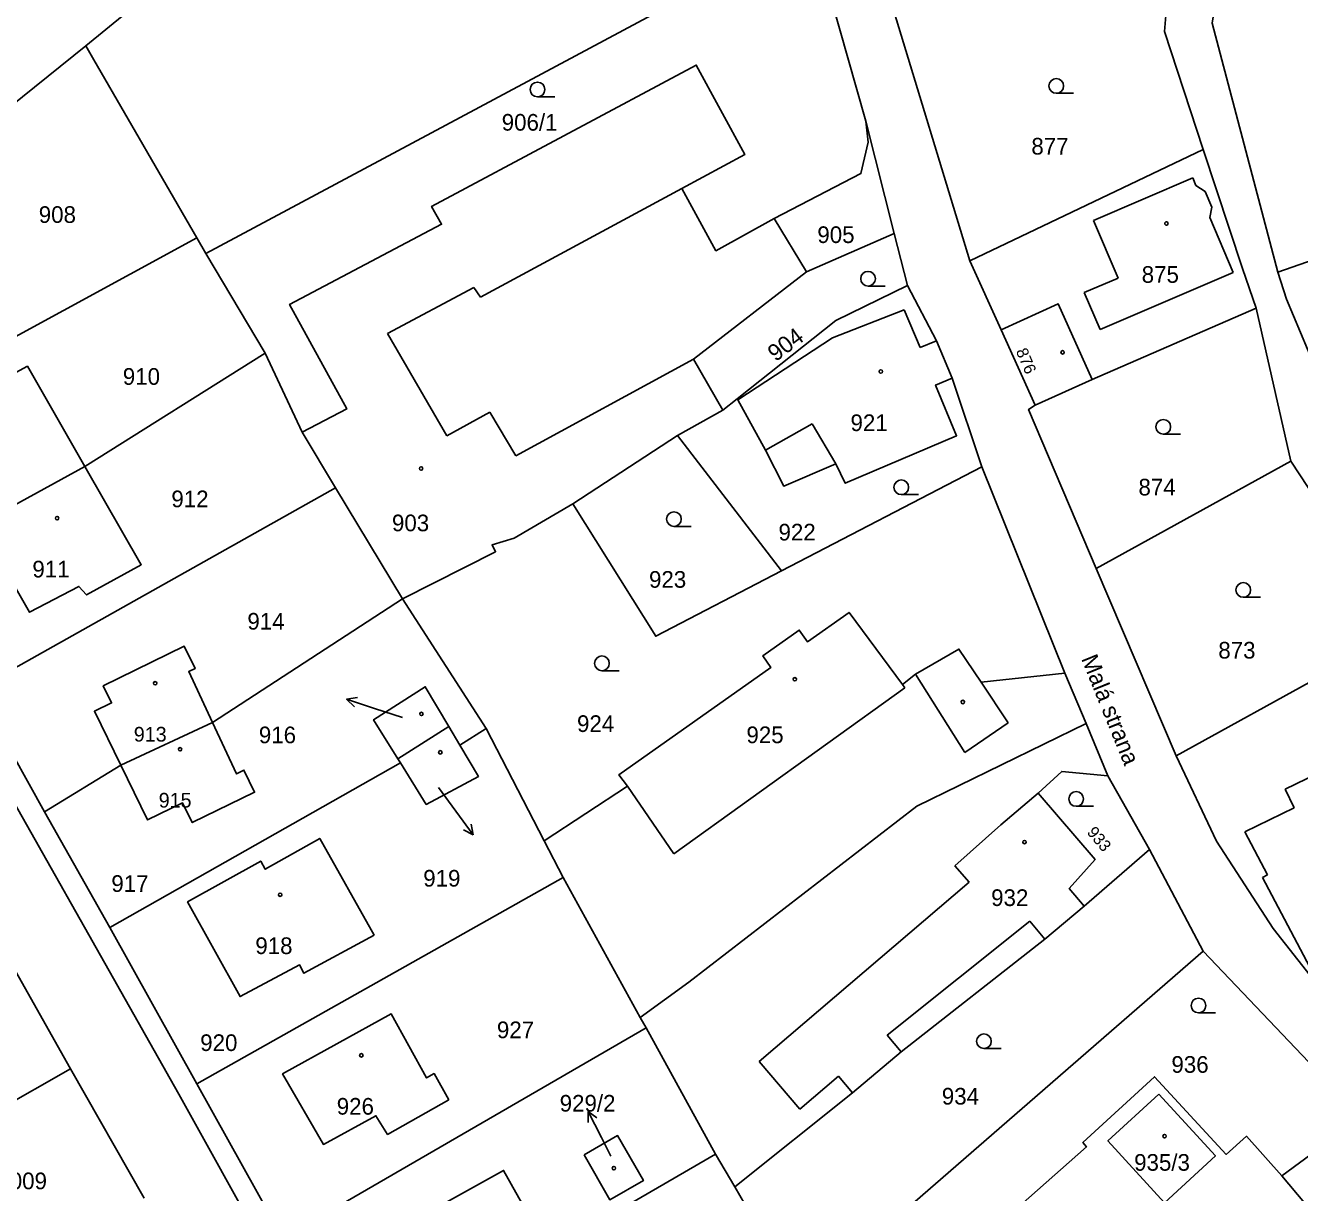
# Model space of a CAD drawing. Extents: x -504988 to -494607, y -1123820 to -1114018.
# Drawn here: x -497675.7 to -497545.8, y -1120128.9 to -1120009.8 of the extents above; entities that cross this region are included whole.
import ezdxf

# ---------------------------------------------------------------- set-up
doc = ezdxf.new("R2010")
doc.units = 0
for name, color, linetype in [('Hranice parcel', 7, 'Continuous'), ('Parcelní čísla', 7, 'Continuous'), ('Pop  PČ popisy', 7, 'Continuous'), ('Vnitřní kresba', 7, 'Continuous'), ('Značky budov', 7, 'Continuous'), ('Značky kultur', 7, 'Continuous')]:
    doc.layers.add(name, color=color, linetype=linetype)

msp = doc.modelspace()

# ---------------------------------------------------------------- linework, layer by layer
at = {"layer": 'Hranice parcel'}
for p, q in [((-497595.51, -1120000.03), (-497657.25, -1120033.08)), ((-497595.51, -1120000.03), (-497589.97, -1120019.6)), ((-497588.93, -1120002.38), (-497579.36, -1120033.84)), ((-497669.5, -1120011.91), (-497661.03, -1120004.98)), ((-497686.75, -1120025.78), (-497669.5, -1120011.91)), ((-497589.97, -1120019.6), (-497587.08, -1120031.04)), ((-497555.57, -1120022.47), (-497579.36, -1120033.84)), ((-497528.79, -1120028.34), (-497547.97, -1120034.99)), ((-497596.03, -1120034.95), (-497599.31, -1120029.53)), ((-497695.36, -1120051.78), (-497658.2, -1120031.49)), ((-497657.25, -1120033.08), (-497658.2, -1120031.49)), ((-497587.08, -1120031.04), (-497596.03, -1120034.95)), ((-497587.08, -1120031.04), (-497585.74, -1120036.35)), ((-497651.22, -1120043.25), (-497657.25, -1120033.08)), ((-497579.36, -1120033.84), (-497576.19, -1120040.86)), ((-497550.18, -1120038.67), (-497566.89, -1120045.94)), ((-497550.18, -1120038.67), (-497546.66, -1120054.28)), ((-497576.19, -1120040.86), (-497572.72, -1120048.57)), ((-497669.6, -1120054.8), (-497651.22, -1120043.25)), ((-497647.44, -1120051.31), (-497651.22, -1120043.25)), ((-497581.17, -1120045.81), (-497578.15, -1120054.86)), ((-497566.89, -1120045.94), (-497572.72, -1120048.57)), ((-497604.55, -1120049.07), (-497603.08, -1120047.91)), ((-497609.19, -1120051.65), (-497604.55, -1120049.07)), ((-497647.44, -1120051.31), (-497644.03, -1120056.98)), ((-497619.86, -1120058.62), (-497609.19, -1120051.65)), ((-497609.19, -1120051.65), (-497598.56, -1120065.46)), ((-497680.39, -1120060.73), (-497669.6, -1120054.8)), ((-497598.56, -1120065.46), (-497578.15, -1120054.86)), ((-497578.15, -1120054.86), (-497569.69, -1120075.9)), ((-497546.66, -1120054.28), (-497566.51, -1120065.23)), ((-497680.65, -1120077.57), (-497644.03, -1120056.98)), ((-497644.03, -1120056.98), (-497637.2, -1120068.32)), ((-497566.51, -1120065.23), (-497558.33, -1120084.33)), ((-497656.59, -1120080.92), (-497637.2, -1120068.32)), ((-497628.7, -1120081.55), (-497637.2, -1120068.32)), ((-497537.01, -1120072.53), (-497558.33, -1120084.33)), ((-497569.69, -1120075.9), (-497567.53, -1120081.03)), ((-497680.65, -1120077.57), (-497673.72, -1120090.03)), ((-497665.93, -1120085.28), (-497656.59, -1120080.92)), ((-497567.53, -1120081.03), (-497565.3, -1120086.35)), ((-497637.69, -1120084.62), (-497632.49, -1120081.33)), ((-497632.49, -1120081.33), (-497631.36, -1120083.23)), ((-497631.36, -1120083.23), (-497628.7, -1120081.55)), ((-497622.76, -1120093), (-497628.7, -1120081.55)), ((-497637.43, -1120085.04), (-497637.69, -1120084.62)), ((-497673.72, -1120090.03), (-497665.93, -1120085.28)), ((-497667.07, -1120101.84), (-497637.43, -1120085.04)), ((-497565.3, -1120086.35), (-497561.06, -1120093.89)), ((-497673.72, -1120090.03), (-497667.07, -1120101.84)), ((-497620.83, -1120096.73), (-497622.76, -1120093)), ((-497567.71, -1120099.67), (-497561.06, -1120093.89)), ((-497561.06, -1120093.89), (-497555.6, -1120104.26)), ((-497658.18, -1120117.79), (-497620.83, -1120096.73)), ((-497620.83, -1120096.73), (-497612.97, -1120111.02)), ((-497667.07, -1120101.84), (-497658.18, -1120117.79)), ((-497596.6, -1120139.88), (-497555.6, -1120104.26)), ((-497555.6, -1120104.26), (-497539.48, -1120121.18)), ((-497677.63, -1120104.59), (-497671.08, -1120116.23)), ((-497649.42, -1120133.52), (-497612.36, -1120112.05)), ((-497612.36, -1120112.05), (-497612.97, -1120111.02)), ((-497612.36, -1120112.05), (-497605.3, -1120124.94)), ((-497671.08, -1120116.23), (-497708.88, -1120137.79)), ((-497671.08, -1120116.23), (-497663.57, -1120129.44)), ((-497658.18, -1120117.79), (-497649.42, -1120133.52)), ((-497547.56, -1120127.17), (-497539.48, -1120121.18)), ((-497605.3, -1120124.94), (-497622.27, -1120134.79)), ((-497603.34, -1120128.29), (-497605.3, -1120124.94)), ((-497543.02, -1120132.55), (-497547.56, -1120127.17)), ((-497598.04, -1120137.4), (-497603.34, -1120128.29))]:
    msp.add_line(p, q, dxfattribs=at)
for points in [[(-497547.97, -1120034.99), (-497554.66, -1120009.59), (-497552.95, -1119999.09)], [(-497559.23, -1120006.74), (-497559.51, -1120010.45), (-497555.57, -1120022.47)], [(-497658.2, -1120031.49), (-497668.68, -1120013.34), (-497669.5, -1120011.91)], [(-497599.31, -1120029.53), (-497605.26, -1120032.81), (-497608.75, -1120026.47), (-497602.33, -1120023), (-497607.26, -1120013.88), (-497634.25, -1120028.28), (-497633.23, -1120030.1), (-497648.72, -1120038.29), (-497642.9, -1120048.94), (-497647.44, -1120051.31)], [(-497589.97, -1120019.6), (-497589.74, -1120021.75), (-497590.48, -1120024.94), (-497599.31, -1120029.53)], [(-497555.57, -1120022.47), (-497551.59, -1120034.63), (-497550.18, -1120038.67)], [(-497604.55, -1120049.07), (-497607.55, -1120043.87), (-497596.03, -1120034.95)], [(-497547.97, -1120034.99), (-497547.09, -1120037.76), (-497541.37, -1120051.36)], [(-497603.08, -1120047.91), (-497593.03, -1120039.92), (-497585.74, -1120036.35)], [(-497585.74, -1120036.35), (-497582.76, -1120041.98), (-497581.17, -1120045.81)], [(-497565.3, -1120246.14), (-497589.23, -1120223.42), (-497599.85, -1120212.32), (-497616.68, -1120192.01), (-497627.04, -1120177.2), (-497636.91, -1120159.82), (-497651.33, -1120134.51), (-497660.03, -1120118.82), (-497706.21, -1120037.1)], [(-497576.19, -1120040.86), (-497570.36, -1120038.23), (-497566.89, -1120045.94)], [(-497669.6, -1120054.8), (-497675.46, -1120044.59), (-497680.85, -1120047.49), (-497680.18, -1120048.78), (-497685.55, -1120051.79), (-497680.39, -1120060.73)], [(-497603.08, -1120047.91), (-497603.02, -1120048.02), (-497600.22, -1120053.16), (-497598.35, -1120056.81), (-497593.05, -1120054.54), (-497592.07, -1120056.53), (-497580.72, -1120051.68), (-497582.87, -1120046.51), (-497581.17, -1120045.81)], [(-497572.72, -1120048.57), (-497573.39, -1120048.99), (-497566.51, -1120065.23)], [(-497680.39, -1120060.73), (-497675.23, -1120069.68), (-497670.2, -1120067.05), (-497669.42, -1120067.91), (-497663.85, -1120064.83), (-497669.6, -1120054.8)], [(-497546.66, -1120054.28), (-497540.5, -1120063.61), (-497537.01, -1120072.53)], [(-497637.2, -1120068.32), (-497627.72, -1120063.5), (-497628.09, -1120062.79), (-497625.84, -1120062.11), (-497619.86, -1120058.62)], [(-497619.86, -1120058.62), (-497611.39, -1120072.13), (-497598.56, -1120065.46)], [(-497622.76, -1120093), (-497614.27, -1120087.42), (-497615.17, -1120086.27), (-497599.65, -1120075.31), (-497600.48, -1120074.13), (-497596.77, -1120071.5), (-497595.93, -1120072.69), (-497591.68, -1120069.69), (-497586.25, -1120077.06), (-497584.93, -1120075.98), (-497580.48, -1120073.43), (-497578.23, -1120076.8), (-497569.69, -1120075.9)], [(-497656.59, -1120080.92), (-497659, -1120075.73), (-497658.37, -1120075.42), (-497659.46, -1120073.15), (-497667.72, -1120077.19), (-497666.87, -1120078.92), (-497668.63, -1120079.78), (-497665.93, -1120085.28)], [(-497632.49, -1120081.33), (-497634.89, -1120077.28), (-497640.16, -1120080.64), (-497637.69, -1120084.62)], [(-497665.93, -1120085.28), (-497663.21, -1120090.86), (-497659.63, -1120089.12), (-497658.65, -1120091.13), (-497652.3, -1120088.03), (-497653.38, -1120085.78), (-497654.15, -1120086.16), (-497656.59, -1120080.92)], [(-497612.97, -1120111.02), (-497608.02, -1120107.42), (-497584.77, -1120089.47), (-497567.53, -1120081.03)], [(-497637.43, -1120085.04), (-497634.79, -1120089.28), (-497629.47, -1120086.42), (-497631.36, -1120083.23)], [(-497558.33, -1120084.33), (-497554.21, -1120093.02), (-497548.46, -1120101.92), (-497543.43, -1120108.32)], [(-497567.71, -1120099.67), (-497569.23, -1120097.85), (-497566.61, -1120094.9), (-497572.39, -1120088.12), (-497570, -1120085.92), (-497565.3, -1120086.35)], [(-497640.12, -1120102.62), (-497645.65, -1120092.74), (-497651.21, -1120095.89), (-497651.67, -1120095.06), (-497659.12, -1120099.23), (-497653.78, -1120108.88), (-497647.7, -1120105.65), (-497647.27, -1120106.5), (-497640.12, -1120102.62)], [(-497603.34, -1120128.29), (-497591.33, -1120118.68), (-497586.38, -1120114.5), (-497571.74, -1120103.01), (-497567.71, -1120099.67)], [(-497632.49, -1120119.42), (-497634, -1120116.73), (-497634.76, -1120117.17), (-497638.38, -1120110.63), (-497649.44, -1120116.77), (-497645.27, -1120123.96), (-497639.93, -1120121.03), (-497638.73, -1120122.93), (-497632.49, -1120119.42)], [(-497547.56, -1120127.17), (-497551.18, -1120123.12), (-497553.25, -1120124.98), (-497560.54, -1120117.05), (-497567.85, -1120123.76), (-497567.49, -1120124.21), (-497592.77, -1120146.58)], [(-497560.09, -1120118.82), (-497554.33, -1120125.13), (-497559.51, -1120129.92), (-497565.3, -1120123.6), (-497560.09, -1120118.82)], [(-497618.71, -1120125.01), (-497615.29, -1120123.05), (-497612.66, -1120127.65), (-497616.08, -1120129.6), (-497618.71, -1120125.01)], [(-497622.27, -1120134.79), (-497624.28, -1120131.33), (-497626.91, -1120126.6), (-497638.61, -1120133.1), (-497633.81, -1120141.47)]]:
    msp.add_lwpolyline(points, dxfattribs=at)
at = {"layer": 'Pop  PČ popisy'}
for p, q in [((-497642.91, -1120078.55), (-497641.81, -1120078.39)), ((-497640.06, -1120079.48), (-497642.91, -1120078.55)), ((-497642.91, -1120078.55), (-497642.12, -1120079.34)), ((-497637.21, -1120080.41), (-497640.06, -1120079.48)), ((-497633.55, -1120087.54), (-497631.78, -1120089.96)), ((-497631.78, -1120089.96), (-497630.02, -1120092.39)), ((-497630.02, -1120092.39), (-497630.2, -1120091.28)), ((-497630.02, -1120092.39), (-497631.01, -1120091.87)), ((-497616.93, -1120123.26), (-497618.29, -1120120.59)), ((-497618.29, -1120120.59), (-497617.39, -1120121.25)), ((-497618.29, -1120120.59), (-497618.28, -1120121.71)), ((-497615.97, -1120125.14), (-497616.93, -1120123.26))]:
    msp.add_line(p, q, dxfattribs=at)
at = {"layer": 'Vnitřní kresba'}
for p, q in [((-497608.75, -1120026.47), (-497629.28, -1120037.55)), ((-497566.77, -1120029.73), (-497556.65, -1120025.38)), ((-497556.65, -1120025.38), (-497556.32, -1120026.15)), ((-497556.32, -1120026.15), (-497555.39, -1120026.78)), ((-497555.39, -1120026.78), (-497554.71, -1120028.38)), ((-497554.71, -1120028.38), (-497554.92, -1120029.42)), ((-497564.26, -1120035.59), (-497566.77, -1120029.73)), ((-497554.92, -1120029.42), (-497552.51, -1120035.02)), ((-497552.51, -1120035.02), (-497566.1, -1120040.85)), ((-497629.94, -1120036.55), (-497638.73, -1120041.24)), ((-497629.28, -1120037.55), (-497629.94, -1120036.55)), ((-497567.72, -1120037.08), (-497564.26, -1120035.59)), ((-497566.1, -1120040.85), (-497567.72, -1120037.08)), ((-497593.36, -1120041.69), (-497586.06, -1120038.82)), ((-497586.06, -1120038.82), (-497584.45, -1120042.69)), ((-497638.73, -1120041.24), (-497632.7, -1120051.7)), ((-497593.36, -1120041.69), (-497603.02, -1120048.02)), ((-497584.45, -1120042.69), (-497582.76, -1120041.98)), ((-497625.67, -1120053.73), (-497607.55, -1120043.87)), ((-497632.7, -1120051.7), (-497628.32, -1120049.26)), ((-497628.32, -1120049.26), (-497625.67, -1120053.73)), ((-497595.44, -1120050.46), (-497600.22, -1120053.16)), ((-497593.05, -1120054.54), (-497595.44, -1120050.46)), ((-497586.25, -1120077.06), (-497586.01, -1120077.39)), ((-497579.88, -1120083.97), (-497584.93, -1120075.98)), ((-497578.23, -1120076.8), (-497575.45, -1120080.96)), ((-497586.01, -1120077.39), (-497609.56, -1120094.31)), ((-497575.45, -1120080.96), (-497579.88, -1120083.97)), ((-497547.21, -1120087.73), (-497541.53, -1120084.95)), ((-497609.56, -1120094.31), (-497614.27, -1120087.42)), ((-497576.21, -1120091.35), (-497572.39, -1120088.12)), ((-497546.29, -1120089.61), (-497547.21, -1120087.73)), ((-497551.32, -1120092.07), (-497546.29, -1120089.61)), ((-497580.89, -1120095.53), (-497576.21, -1120091.35)), ((-497549.01, -1120096.47), (-497551.32, -1120092.07)), ((-497579.44, -1120097.22), (-497580.89, -1120095.53)), ((-497549.52, -1120096.74), (-497549.01, -1120096.47)), ((-497600.84, -1120115.49), (-497579.44, -1120097.22)), ((-497543.43, -1120108.32), (-497549.52, -1120096.74)), ((-497573.25, -1120101.19), (-497587.8, -1120112.82)), ((-497571.74, -1120103.01), (-497573.25, -1120101.19)), ((-497587.8, -1120112.82), (-497586.38, -1120114.5)), ((-497596.72, -1120120.36), (-497600.84, -1120115.49)), ((-497592.75, -1120117), (-497596.72, -1120120.36)), ((-497591.33, -1120118.68), (-497592.75, -1120117))]:
    msp.add_line(p, q, dxfattribs=at)
at = {"layer": 'Značky budov'}
for centre in [(-497559.33, -1120030.03), (-497569.92, -1120043.17), (-497588.45, -1120045.12), (-497635.32, -1120055.02), (-497672.43, -1120060.08), (-497662.43, -1120076.92), (-497597.22, -1120076.51), (-497580.09, -1120078.83), (-497635.29, -1120080.05), (-497659.89, -1120083.65), (-497633.36, -1120083.97), (-497573.8, -1120093.12), (-497649.69, -1120098.49), (-497641.41, -1120114.87), (-497559.52, -1120123.11), (-497615.66, -1120126.38)]:
    msp.add_circle(centre, 0.175, dxfattribs=at)
at = {"layer": 'Značky kultur'}
for p, q in [((-497623.45, -1120017.11), (-497621.7, -1120017.11)), ((-497570.56, -1120016.75), (-497568.81, -1120016.75)), ((-497589.75, -1120036.41), (-497588, -1120036.41)), ((-497559.65, -1120051.52), (-497557.9, -1120051.52)), ((-497586.36, -1120057.68), (-497584.61, -1120057.68)), ((-497609.54, -1120060.93), (-497607.79, -1120060.93)), ((-497551.5, -1120068.15), (-497549.75, -1120068.15)), ((-497616.88, -1120075.64), (-497615.13, -1120075.64)), ((-497568.53, -1120089.47), (-497566.78, -1120089.47)), ((-497556.06, -1120110.54), (-497554.31, -1120110.54)), ((-497577.94, -1120114.18), (-497576.19, -1120114.18))]:
    msp.add_line(p, q, dxfattribs=at)
for centre in [(-497623.45, -1120016.36), (-497570.56, -1120016), (-497589.75, -1120035.66), (-497559.65, -1120050.77), (-497586.36, -1120056.93), (-497609.54, -1120060.18), (-497551.5, -1120067.4), (-497616.88, -1120074.89), (-497568.53, -1120088.72), (-497556.06, -1120109.79), (-497577.94, -1120113.43)]:
    msp.add_circle(centre, 0.75, dxfattribs=at)

# ---------------------------------------------------------------- texts
at = {"layer": 'Parcelní čísla'}
for s, height, p in [('906/1', 1.7, (-497627.1, -1120020.56)), ('877', 1.7, (-497573.1, -1120023)), ('908', 1.7, (-497674.3, -1120029.97)), ('905', 1.7, (-497594.92, -1120032.02)), ('875', 1.7, (-497561.85, -1120036.08)), ('910', 1.7, (-497665.73, -1120046.48)), ('921', 1.7, (-497591.54, -1120051.2)), ('874', 1.7, (-497562.18, -1120057.77)), ('912', 1.7, (-497660.78, -1120058.97)), ('903', 1.7, (-497638.29, -1120061.42)), ('922', 1.7, (-497598.88, -1120062.36)), ('911', 1.7, (-497674.95, -1120066.13)), ('923', 1.7, (-497612.08, -1120067.18)), ('914', 1.7, (-497653.03, -1120071.45)), ('873', 1.7, (-497554.04, -1120074.4)), ('924', 1.7, (-497619.42, -1120081.89)), ('913', 1.5, (-497664.61, -1120082.87)), ('916', 1.7, (-497651.86, -1120083.04)), ('925', 1.7, (-497602.15, -1120083.03)), ('915', 1.5, (-497662.07, -1120089.6)), ('917', 1.7, (-497666.9, -1120098.2)), ('919', 1.7, (-497635.1, -1120097.66)), ('932', 1.7, (-497577.2, -1120099.64)), ('918', 1.7, (-497652.22, -1120104.54)), ('927', 1.7, (-497627.59, -1120113.12)), ('920', 1.7, (-497657.84, -1120114.43)), ('936', 1.7, (-497558.82, -1120116.65)), ('934', 1.7, (-497582.23, -1120119.89)), ('926', 1.7, (-497643.92, -1120120.92)), ('929/2', 1.7, (-497621.19, -1120120.61)), ('935/3', 1.7, (-497562.62, -1120126.64)), ('1009', 1.7, (-497678.52, -1120128.53))]:
    msp.add_text(s, height=height, dxfattribs=at).set_placement(p)
for s, height, rotation, p in [('904', 1.7, 37, (-497599.17, -1120044.18)), ('876', 1.2, 293, (-497574.7, -1120043.04)), ('933', 1.2, 310, (-497567.5, -1120092.16))]:
    msp.add_text(s, height=height, rotation=rotation, dxfattribs=at).set_placement(p)
at = {"layer": 'Pop  PČ popisy'}
msp.add_text('Malá strana', height=1.7, rotation=292, dxfattribs=at).set_placement((-497568.04, -1120074.41))

doc.saveas('drawing.dxf')
